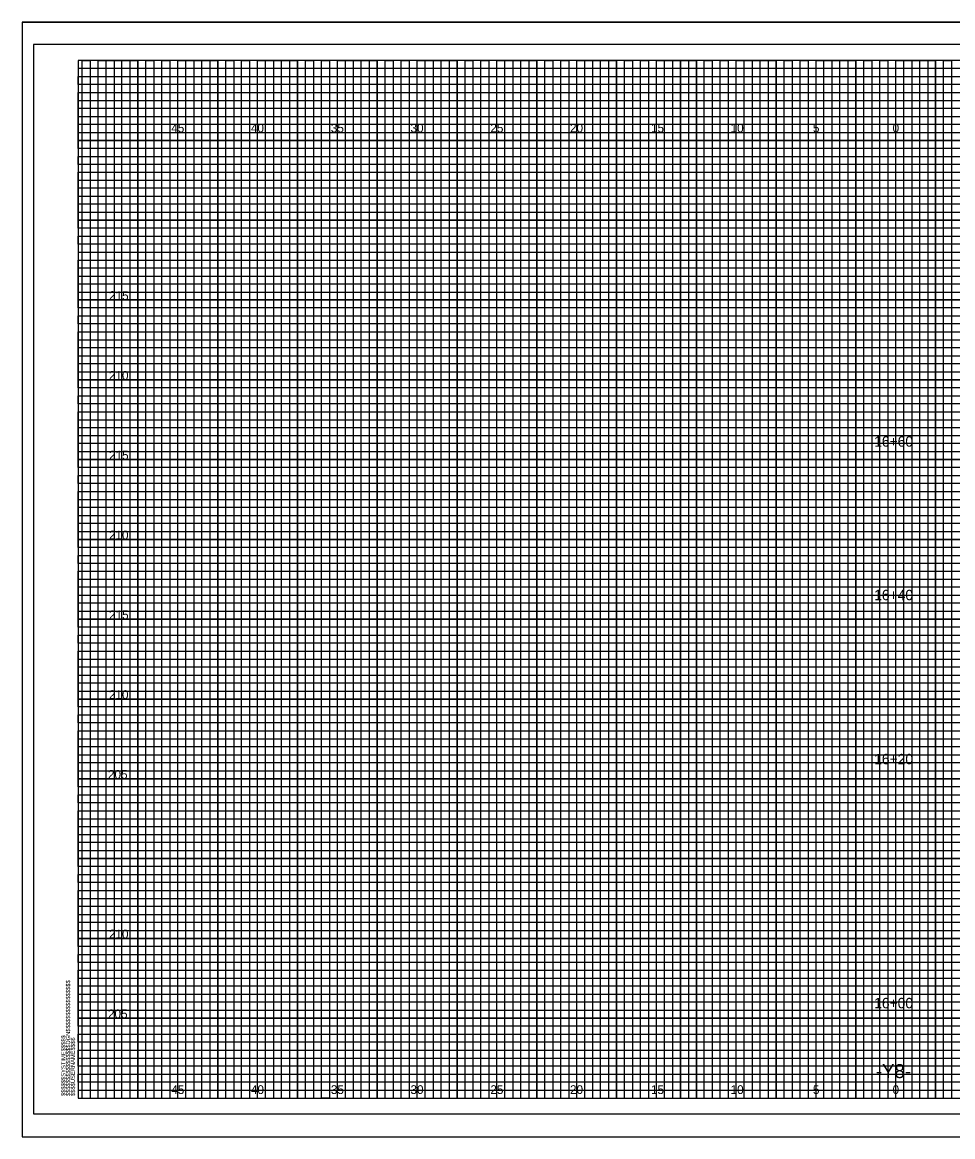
# Model space of a CAD drawing. Extents: x -4 to 103, y -2 to 209.
# Drawn here: x -3.5 to 54.8, y 139.2 to 209.1 of the extents above; entities that cross this region are included whole.
import ezdxf

# ---------------------------------------------------------------- set-up
doc = ezdxf.new("R2010")
doc.units = 0
for name, color, linetype in [('Old_Level_10', 7, 'Continuous'), ('Old_Level_16', 7, 'Continuous'), ('Old_Level_17', 7, 'Continuous'), ('Old_Level_3', 7, 'Continuous'), ('Old_Level_5', 7, 'Continuous'), ('Old_Level_6', 7, 'Continuous'), ('Old_Level_8', 7, 'Continuous'), ('Prop Dimension', 7, 'Continuous'), ('Prop Terminator CELL', 7, 'Continuous'), ('Prop XSC Text', 7, 'Continuous'), ('Typical Curb CELL', 7, 'Continuous')]:
    doc.layers.add(name, color=color, linetype=linetype)

msp = doc.modelspace()

# ---------------------------------------------------------------- linework, layer by layer
at = {"layer": 'Old_Level_10'}
for p, q in [((1.25, 141.65), (1.25, 206.65)), ((3.75, 141.65), (3.75, 206.65)), ((6.25, 141.65), (6.25, 206.65)), ((8.75, 141.65), (8.75, 206.65)), ((11.25, 141.65), (11.25, 206.65)), ((13.75, 141.65), (13.75, 206.65)), ((16.25, 141.65), (16.25, 206.65)), ((18.75, 141.65), (18.75, 206.65)), ((21.25, 141.65), (21.25, 206.65)), ((23.75, 141.65), (23.75, 206.65)), ((26.25, 141.65), (26.25, 206.65)), ((28.75, 141.65), (28.75, 206.65)), ((31.25, 141.65), (31.25, 206.65)), ((33.75, 141.65), (33.75, 206.65)), ((36.25, 141.65), (36.25, 206.65)), ((38.75, 141.65), (38.75, 206.65)), ((41.25, 141.65), (41.25, 206.65)), ((43.75, 141.65), (43.75, 206.65)), ((46.25, 141.65), (46.25, 206.65)), ((48.75, 141.65), (48.75, 206.65)), ((51.25, 141.65), (51.25, 206.65)), ((53.75, 141.65), (53.75, 206.65)), ((0, 204.15), (74.25, 204.15)), ((0, 201.65), (102.5, 201.65)), ((0, 199.15), (102.5, 199.15)), ((0, 196.65), (102.5, 196.65)), ((0, 194.15), (102.5, 194.15)), ((0, 191.65), (102.5, 191.65)), ((0, 189.15), (102.5, 189.15)), ((0, 186.65), (102.5, 186.65)), ((0, 184.15), (102.5, 184.15)), ((0, 181.65), (102.5, 181.65)), ((0, 179.15), (102.5, 179.15)), ((0, 176.65), (102.5, 176.65)), ((0, 174.15), (102.5, 174.15)), ((0, 171.65), (102.5, 171.65)), ((0, 169.15), (102.5, 169.15)), ((0, 166.65), (102.5, 166.65)), ((0, 164.15), (102.5, 164.15)), ((0, 161.65), (102.5, 161.65)), ((0, 159.15), (102.5, 159.15)), ((0, 156.65), (102.5, 156.65)), ((0, 154.15), (102.5, 154.15)), ((0, 151.65), (102.5, 151.65)), ((0, 149.15), (102.5, 149.15)), ((0, 146.65), (102.5, 146.65)), ((0, 144.15), (102.5, 144.15))]:
    msp.add_line(p, q, dxfattribs=at)
at = {"layer": 'Old_Level_17'}
for points in [[(0, 203.65), (0, 204.65), (74.25, 204.65), (74.25, 205.15), (0, 205.15), (0, 205.65), (74.25, 205.65), (74.25, 206.15), (0, 206.15)], [(0.25, 141.65), (0.25, 206.65), (0.75, 206.65), (0.75, 141.65), (1.75, 141.65), (1.75, 206.65), (2.25, 206.65), (2.25, 141.65), (2.75, 141.65), (2.75, 206.65), (3.25, 206.65), (3.25, 141.65), (4.25, 141.65), (4.25, 206.65), (4.75, 206.65), (4.75, 141.65), (5.25, 141.65), (5.25, 206.65), (5.75, 206.65), (5.75, 141.65), (6.75, 141.65), (6.75, 206.65), (7.25, 206.65), (7.25, 141.65), (7.75, 141.65), (7.75, 206.65), (8.25, 206.65), (8.25, 141.65), (9.25, 141.65), (9.25, 206.65), (9.75, 206.65), (9.75, 141.65), (10.25, 141.65), (10.25, 206.65), (10.75, 206.65), (10.75, 141.65), (11.75, 141.65), (11.75, 206.65), (12.25, 206.65), (12.25, 141.65), (12.75, 141.65), (12.75, 206.65), (13.25, 206.65), (13.25, 141.65), (14.25, 141.65), (14.25, 206.65), (14.75, 206.65), (14.75, 141.65), (15.75, 141.65), (15.25, 141.65), (15.25, 206.65), (15.75, 206.65), (15.75, 141.65), (16.75, 141.65), (16.75, 206.65), (17.25, 206.65), (17.25, 141.65), (17.75, 141.65), (17.75, 206.65), (18.25, 206.65), (18.25, 141.65), (19.25, 141.65), (19.25, 206.65), (19.75, 206.65), (19.75, 141.65), (20.25, 141.65), (20.25, 206.65), (20.75, 206.65), (20.75, 141.65), (21.75, 141.65), (21.75, 206.65), (22.25, 206.65), (22.25, 141.65), (22.75, 141.65), (22.75, 206.65), (23.25, 206.65), (23.25, 141.65), (24.25, 141.65), (24.25, 206.65), (24.75, 206.65), (24.75, 141.65), (25.25, 141.65), (25.25, 206.65), (25.75, 206.65), (25.75, 141.65), (26.75, 141.65), (26.75, 206.65), (27.25, 206.65), (27.25, 141.65), (27.75, 141.65), (27.75, 206.65), (28.25, 206.65), (28.25, 141.65), (29.25, 141.65), (29.25, 206.65), (29.75, 206.65), (29.75, 141.65), (30.25, 141.65), (30.25, 206.65), (30.75, 206.65), (30.75, 141.65)], [(30.75, 141.65), (31.75, 141.65), (31.75, 206.65), (32.25, 206.65), (32.25, 141.65), (32.75, 141.65), (32.75, 206.65), (33.25, 206.65), (33.25, 141.65), (34.25, 141.65), (34.25, 206.65), (34.75, 206.65), (34.75, 141.65), (35.25, 141.65), (35.25, 206.65), (35.75, 206.65), (35.75, 141.65), (36.75, 141.65), (36.75, 206.65), (37.25, 206.65), (37.25, 141.65), (37.75, 141.65), (37.75, 206.65), (37.75, 141.65)], [(38.25, 206.65), (38.25, 141.65), (39.25, 141.65), (39.25, 206.65), (39.75, 206.65), (39.75, 141.65), (40.25, 141.65), (40.25, 206.65), (40.75, 206.65), (40.75, 141.65), (41.75, 141.65), (41.75, 206.65), (42.25, 206.65), (42.25, 141.65), (42.75, 141.65), (42.75, 206.65), (43.25, 206.65), (43.25, 141.65), (43.75, 141.65), (44.25, 141.65), (44.25, 206.65), (44.75, 206.65), (44.75, 141.65), (45.25, 141.65), (45.25, 206.65), (45.75, 206.65), (45.75, 141.65), (46.75, 141.65), (46.75, 206.65), (47.25, 206.65), (47.25, 141.65), (47.75, 141.65), (47.75, 206.65), (48.25, 206.65), (48.25, 141.65), (49.25, 141.65), (49.25, 206.65), (49.75, 206.65), (49.75, 141.65), (50.25, 141.65), (50.25, 206.65), (50.75, 206.65), (50.75, 141.65), (51.75, 141.65), (51.75, 206.65), (52.25, 206.65), (52.25, 141.65), (52.75, 141.65), (52.75, 206.65), (53.25, 206.65), (53.25, 141.65), (54.25, 141.65), (54.25, 206.65), (54.75, 206.65), (54.75, 141.65), (55.25, 141.65)], [(102.5, 203.65), (0, 203.65)], [(102.5, 202.65), (0, 202.65), (0, 203.15), (102.5, 203.15)], [(102.5, 201.15), (0, 201.15), (0, 202.15), (102.5, 202.15)], [(102.5, 200.15), (0, 200.15), (0, 200.65), (102.5, 200.65)], [(102.5, 198.65), (0, 198.65), (0, 199.65), (102.5, 199.65)], [(102.5, 197.65), (0, 197.65), (0, 198.15), (102.5, 198.15)], [(102.5, 196.15), (0, 196.15), (0, 197.15), (102.5, 197.15)], [(102.5, 195.15), (0, 195.15), (0, 195.65), (102.5, 195.65)], [(0, 194.65), (102.5, 194.65)], [(102.5, 193.65), (0, 193.65)], [(102.5, 192.65), (0, 192.65), (0, 193.15), (102.5, 193.15)], [(102.5, 191.15), (0, 191.15), (0, 192.15), (102.5, 192.15)], [(102.5, 190.15), (0, 190.15), (0, 190.65), (102.5, 190.65)], [(102.5, 188.65), (0, 188.65), (0, 189.65), (102.5, 189.65)], [(102.5, 187.65), (0, 187.65), (0, 188.15), (102.5, 188.15)], [(102.5, 186.15), (0, 186.15), (0, 187.15), (102.5, 187.15)], [(102.5, 185.15), (0, 185.15), (0, 185.65), (102.5, 185.65)], [(102.5, 183.65), (0, 183.65), (0, 184.65), (102.5, 184.65)], [(102.5, 182.65), (0, 182.65), (0, 183.15), (102.5, 183.15)], [(102.5, 181.15), (0, 181.15), (0, 182.15), (102.5, 182.15)], [(102.5, 180.15), (0, 180.15), (0, 180.65), (102.5, 180.65)], [(102.5, 178.65), (0, 178.65), (0, 179.65), (102.5, 179.65)], [(102.5, 177.65), (0, 177.65), (0, 178.15), (102.5, 178.15)], [(102.5, 176.15), (0, 176.15), (0, 177.15), (102.5, 177.15)], [(102.5, 175.15), (0, 175.15), (0, 175.65), (102.5, 175.65)], [(102.5, 173.65), (0, 173.65), (0, 174.65), (102.5, 174.65)], [(102.5, 172.65), (0, 172.65), (0, 173.15)], [(0, 173.15), (102.5, 173.15)], [(102.5, 171.15), (0, 171.15), (0, 172.15), (102.5, 172.15)], [(102.5, 170.15), (0, 170.15), (0, 170.65), (102.5, 170.65)], [(102.5, 168.65), (0, 168.65), (0, 169.65), (102.5, 169.65)], [(102.5, 167.65), (0, 167.65), (0, 168.15), (102.5, 168.15)], [(102.5, 166.15), (0, 166.15), (0, 167.15), (102.5, 167.15)], [(102.5, 165.15), (0, 165.15), (0, 165.65), (102.5, 165.65)], [(102.5, 163.65), (0, 163.65), (0, 164.65), (102.5, 164.65)], [(102.5, 162.65), (0, 162.65), (0, 163.15), (102.5, 163.15)], [(102.5, 161.15), (0, 161.15), (0, 162.15), (102.5, 162.15)], [(102.5, 160.15), (0, 160.15), (0, 160.65), (102.5, 160.65)], [(102.5, 158.65), (0, 158.65), (0, 159.65), (102.5, 159.65)], [(102.5, 157.65), (0, 157.65), (0, 158.15), (102.5, 158.15)], [(102.5, 156.15), (0, 156.15), (0, 157.15), (102.5, 157.15)], [(102.5, 155.15), (0, 155.15), (0, 155.65), (102.5, 155.65)], [(102.5, 153.65), (0, 153.65), (0, 154.65), (102.5, 154.65)], [(102.5, 152.65), (0, 152.65), (0, 153.15), (102.5, 153.15)], [(102.5, 151.15), (0, 151.15), (0, 152.15), (102.5, 152.15)], [(102.5, 150.15), (0, 150.15), (0, 150.65), (102.5, 150.65)], [(102.5, 148.65), (0, 148.65), (0, 149.65), (102.5, 149.65)], [(102.5, 147.65), (0, 147.65), (0, 148.15), (102.5, 148.15)], [(102.5, 146.15), (0, 146.15), (0, 147.15), (102.5, 147.15)], [(102.5, 145.15), (0, 145.15), (0, 145.65), (102.5, 145.65)], [(102.5, 143.65), (0, 143.65), (0, 144.65), (102.5, 144.65)], [(102.5, 142.65), (0, 142.65), (0, 143.15), (102.5, 143.15)], [(0, 142.15), (102.5, 142.15)]]:
    msp.add_lwpolyline(points, dxfattribs=at)
at = {"layer": 'Old_Level_3'}
for p, q in [((-3.5, 209.05), (103.4, 209.05)), ((-3.5, 209.05), (-3.5, 139.225)), ((-3.5, 139.225), (103.4, 139.225))]:
    msp.add_line(p, q, dxfattribs=at)
at = {"layer": 'Old_Level_5'}
msp.add_lwpolyline([(103.4, 209.05), (-3.5, 209.05), (-3.5, 139.225), (103.4, 139.225)], close=True, dxfattribs=at)
at = {"layer": 'Old_Level_6'}
msp.add_lwpolyline([(102.5, 206.65), (0, 206.65), (0, 141.65), (102.5, 141.65)], close=True, dxfattribs=at)
at = {"layer": 'Old_Level_8'}
for points in [[(1.25, 141.65), (1.25, 206.65), (3.75, 206.65), (3.75, 141.65), (6.25, 141.65), (6.25, 206.65), (8.75, 206.65), (8.75, 141.65), (11.25, 141.65), (11.25, 206.65), (13.75, 206.65), (13.75, 141.65), (16.25, 141.65), (16.25, 206.65), (18.75, 206.65), (18.75, 141.65), (21.25, 141.65), (21.25, 206.65), (23.75, 206.65), (23.75, 141.65), (26.25, 141.65), (26.25, 206.65), (28.75, 206.65), (28.75, 141.65), (31.25, 141.65), (31.25, 206.65), (33.75, 206.65), (33.75, 141.65), (36.25, 141.65), (36.25, 206.65), (38.75, 206.65), (38.75, 141.65), (41.25, 141.65), (41.25, 206.65), (43.75, 206.65), (43.75, 141.65), (46.25, 141.65), (46.25, 206.65), (48.75, 206.65), (48.75, 141.65), (51.25, 141.65), (51.25, 206.65), (53.75, 206.65), (53.75, 141.65)], [(102.5, 201.65), (0, 201.65), (0, 204.15), (74.25, 204.15)], [(102.5, 196.65), (0, 196.65), (0, 199.15), (102.5, 199.15)], [(102.5, 191.65), (0, 191.65), (0, 194.15), (102.5, 194.15)], [(102.5, 186.65), (0, 186.65), (0, 189.15), (102.5, 189.15)], [(102.5, 181.65), (0, 181.65), (0, 184.15), (102.5, 184.15)], [(102.5, 176.65), (0, 176.65), (0, 179.15), (102.5, 179.15)], [(102.5, 171.65), (0, 171.65), (0, 174.15), (102.5, 174.15)], [(102.5, 166.65), (0, 166.65), (0, 169.15), (102.5, 169.15)], [(102.5, 161.65), (0, 161.65), (0, 164.15), (102.5, 164.15)], [(102.5, 156.65), (0, 156.65), (0, 159.15), (102.5, 159.15)], [(102.5, 151.65), (0, 151.65), (0, 154.15), (102.5, 154.15)], [(102.5, 146.65), (0, 146.65), (0, 149.15), (102.5, 149.15)], [(0, 144.15), (102.5, 144.15)]]:
    msp.add_lwpolyline(points, dxfattribs=at)
at = {"layer": 'Typical Curb CELL'}
msp.add_lwpolyline([(103, 207.65), (-2.8, 207.65), (-2.8, 140.65), (103, 140.65)], close=True, dxfattribs=at)

# ---------------------------------------------------------------- texts
at = {"layer": 'Old_Level_16'}
for s, p in [('45', (5.8399, 202.15)), ('40', (10.8313, 202.15)), ('35', (15.8399, 202.15)), ('30', (20.8313, 202.15)), ('25', (25.8399, 202.15)), ('20', (30.8313, 202.15)), ('15', (35.9058, 202.15)), ('10', (40.8971, 202.15)), ('5', (46.0574, 202.15)), ('0', (51.0488, 202.15)), ('0', (51.0488, 202.15)), ('45', (5.8399, 141.9)), ('40', (10.8313, 141.9)), ('35', (15.8399, 141.9)), ('30', (20.8313, 141.9)), ('25', (25.8399, 141.9)), ('20', (30.8313, 141.9)), ('15', (35.9058, 141.9)), ('10', (40.8971, 141.9)), ('5', (46.0574, 141.9)), ('0', (51.0488, 141.9)), ('0', (51.0488, 141.9))]:
    msp.add_text(s, height=0.55, dxfattribs=at).set_placement(p)
at = {"layer": 'Old_Level_6'}
for s, p in [('$$$$$$$$$$$$$$$$DGN$$$$$$$$$$$$$$$$', (-0.5, 141.775)), ('$$$$$$SYSTIME$$$$$', (-0.7973, 141.7747)), ('$$$$USERNAME$$$$', (-0.2, 141.775))]:
    msp.add_text(s, height=0.2625, rotation=90, dxfattribs=at).set_placement(p)
at = {"layer": 'Old_Level_8'}
msp.add_text('040397', height=0.0025, rotation=90, dxfattribs=at).set_placement((-0.0007, 206.6364))
at = {"layer": 'Prop Dimension'}
for s, p in [('215', (1.9383, 191.65)), ('210', (1.9296, 186.65)), ('215', (1.9383, 181.65)), ('210', (1.9296, 176.65)), ('215', (1.9383, 171.65)), ('210', (1.9296, 166.65)), ('205', (1.8724, 161.65)), ('210', (1.9296, 151.65)), ('205', (1.8724, 146.65))]:
    msp.add_text(s, height=0.55, dxfattribs=at).set_placement(p)
at = {"layer": 'Prop Terminator CELL'}
for s, p in [('16+60', (49.8934, 182.4618)), ('16+40', (49.8934, 172.8405)), ('16+20', (49.8934, 162.5604)), ('16+00', (49.8934, 147.2724))]:
    msp.add_text(s, height=0.65, dxfattribs=at).set_placement(p)
at = {"layer": 'Prop XSC Text'}
msp.add_text('-Y8-', height=0.875, dxfattribs=at).set_placement((49.9985, 142.9))

doc.saveas('drawing.dxf')
